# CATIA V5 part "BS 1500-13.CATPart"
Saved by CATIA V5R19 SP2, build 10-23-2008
Part number: BS 1500-13
Bounding box of the stored display mesh (mm): x -31.459 to 31.459, y -31.459 to 31.459, z 0 to 70
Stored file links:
  C:\Users\Bora\Desktop\3D Katı model\BS serisi\BS 1500\BS 1500-13.CATPart
  C:\Program Files\Dassault Systemes\B19\intel_a\reffiles\standard\MetricThickPitch.txt
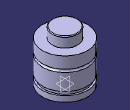
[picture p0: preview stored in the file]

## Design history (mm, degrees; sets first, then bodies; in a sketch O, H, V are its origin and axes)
Body1 (main body)
  Sketch1 on yz-plane, origin (0, 0, 0), H (0, 1, 0), V (0, 0, 1)
    point P1 (31.5, 40)
    point P2 (31.5, 36)
    point P3 (31.5, 40)
    point P7 (18, 69)
    point P9 (18, 69)
    point P14 (31.5, 36)
    arc A1 centre (31.5, 38) radius 2 from (31.5, 40) to (31.5, 36) ccw
    line L1 (31.5, 40) -> (31.5, 56)
    line L2 (31.5, 0) -> (31.5, 8)
    arc A2 centre (17, 69) radius 1 from (18, 69) to (17, 70) ccw
    line L3 (18, 69) -> (18, 56)
    line L4 (29, 13) -> (29, 8)
    line L5 (31.5, 13) -> (31.5, 36)
    line L6 (17, 70) -> (0, 70)
    point P15 (0, 70)
    line L7 (18, 56) -> (31.5, 56)
    line L8 (0, 0) -> (31.5, 0)
    line L9 (29, 13) -> (31.5, 13)
    line L10 (29, 8) -> (31.5, 8)
    tangency: L6 A2
    coincidence: P15 V, P1 P3, P2 P14, P7 P9
    horizontal: L7 H, L8 H, L9 H, L10 H
  Shaft1: profile Sketch1, axis Sketch1.V, angle 360
  Sketch2 on face of Shaft1 from Sketch1.L8, origin (0, 0, 0), H (1, 0, 0), V (0, -1, 0)
    point P1 (10, 0)
    distance P1 V = 10
  Hole1: placed by Sketch2, at (10, 0, 0) direction (0, 0, 1), diameter 6.647, depth 5, threaded "M8", thread diameter 8, thread depth 5, pitch 1.25
  CircPattern1: of Hole1, instances 2, angular step 180, axis from xy-plane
